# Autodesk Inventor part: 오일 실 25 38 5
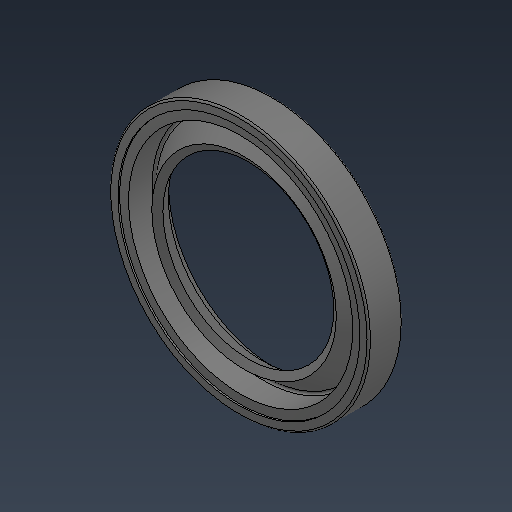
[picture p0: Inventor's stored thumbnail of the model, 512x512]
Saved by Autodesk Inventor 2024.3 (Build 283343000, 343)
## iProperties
Created: 2025-07
Part Number: 오일 실 25 38 5
Material: 고무
Description: 오일 실 - 비스프링, 조립 GA
Document SubType Name: Modeling
Designer: user
Density: 0.93 g/cm^3
Appearance: 기본값
Sending System: Autodesk Inventor 2026
Preprocessor: ST-DEVELOPER v20.1
Author: jhkim
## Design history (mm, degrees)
feature "Solid1"
node "솔리드1"
